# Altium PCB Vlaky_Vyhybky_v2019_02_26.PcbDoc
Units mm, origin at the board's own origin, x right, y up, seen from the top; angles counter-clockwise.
Board outline 140 x 100 mm, 2 copper layers (Top Layer, Bottom Layer); 83 components, 61 nets, 264 pads, 44 vias.
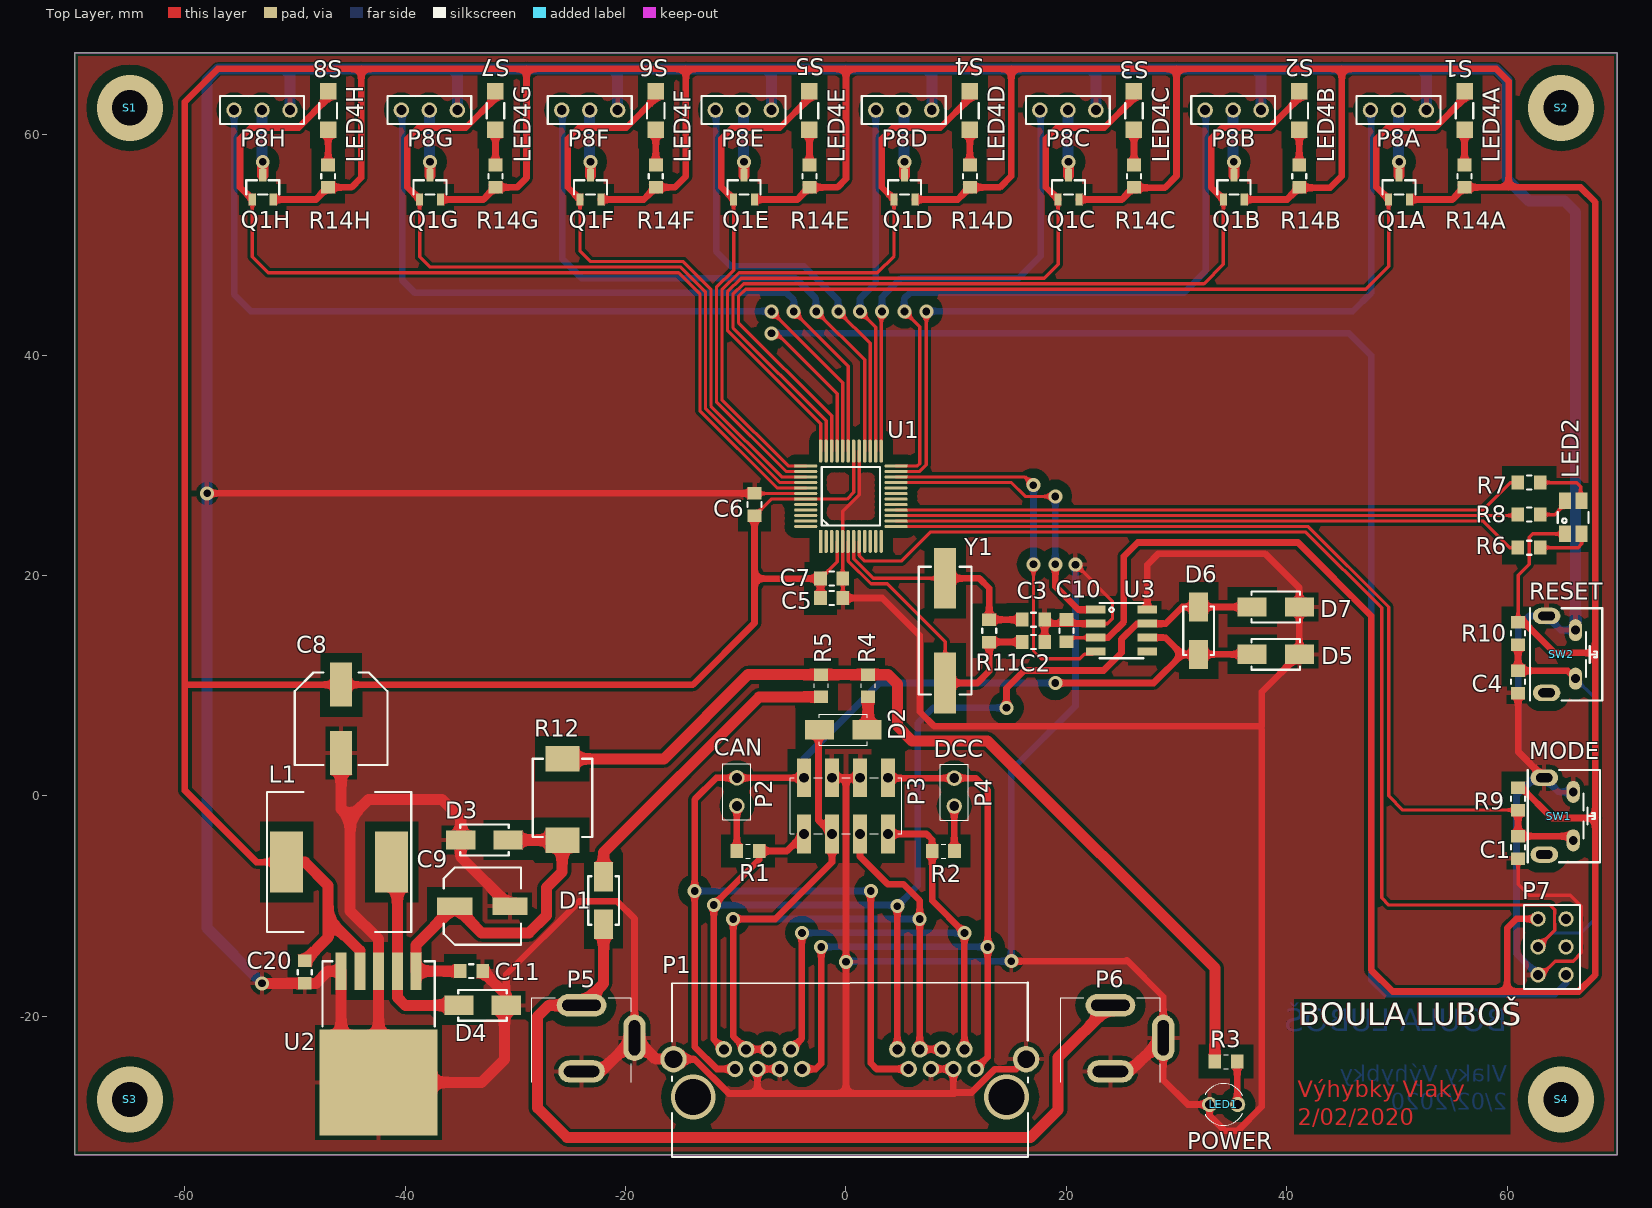
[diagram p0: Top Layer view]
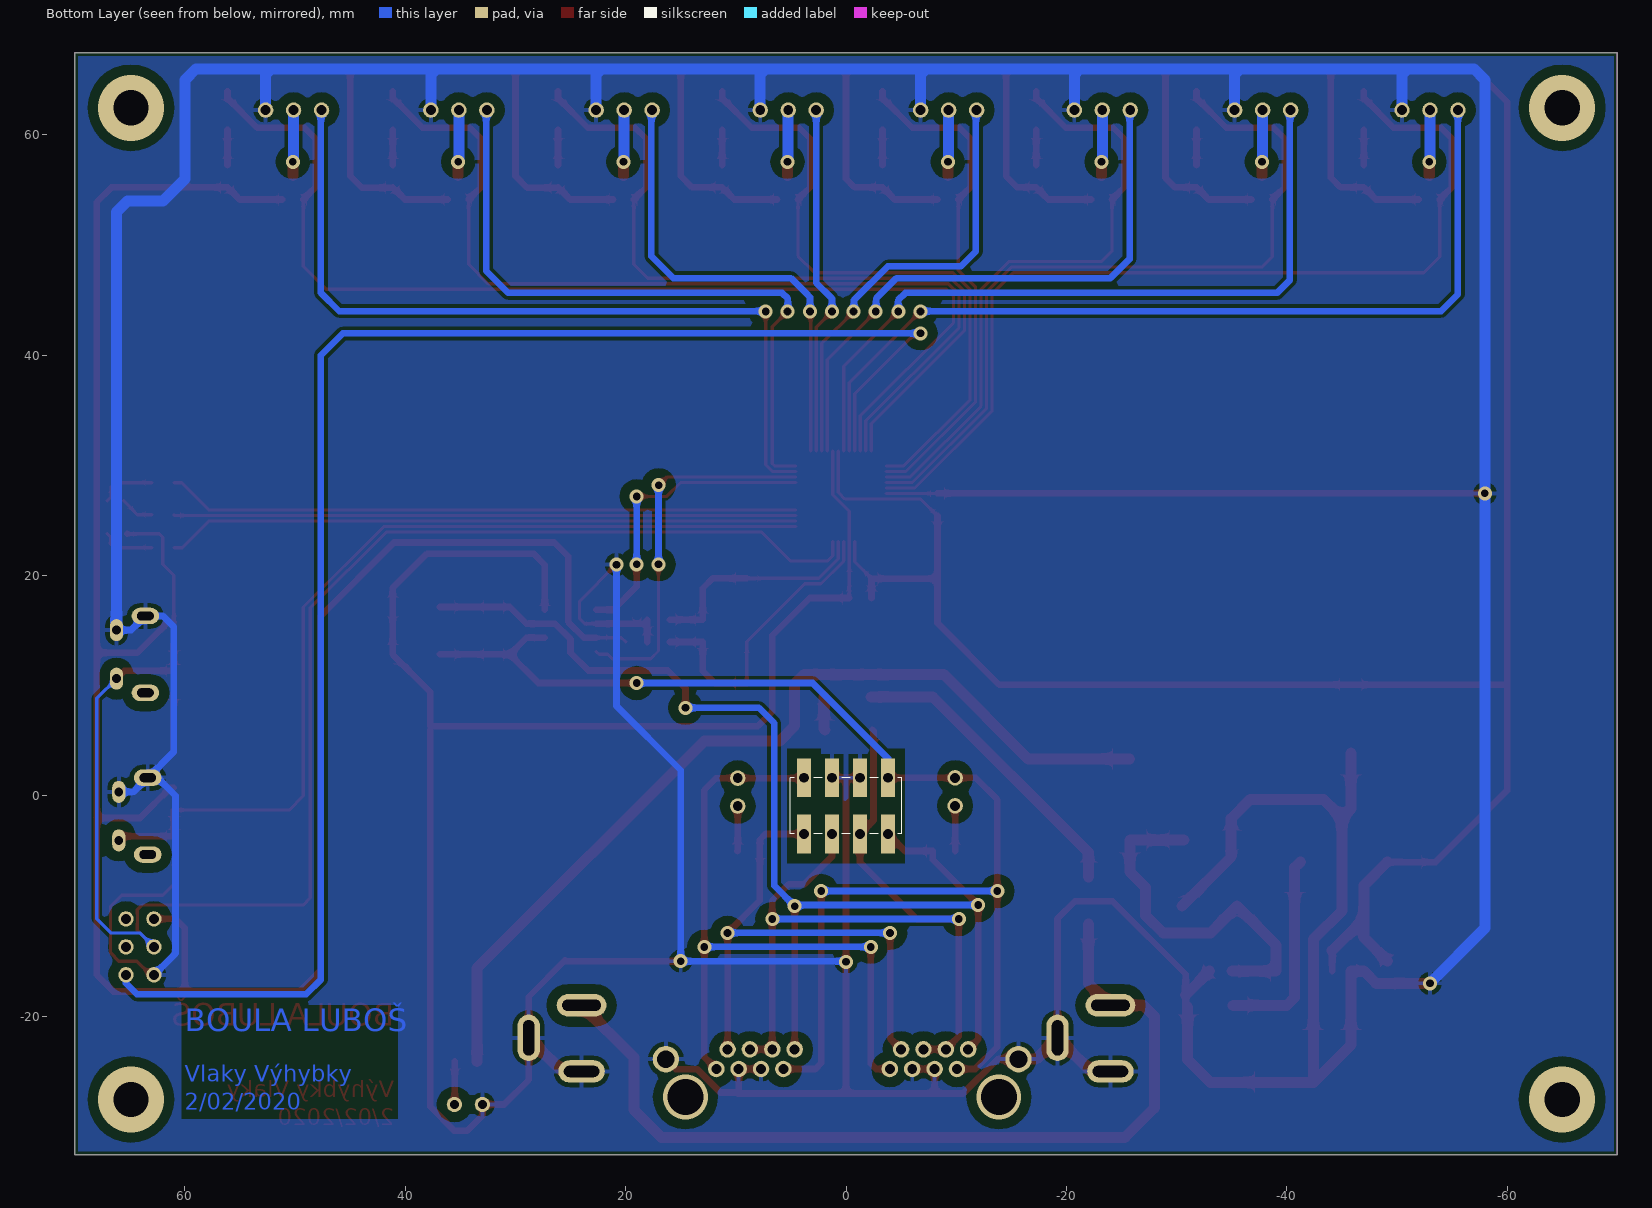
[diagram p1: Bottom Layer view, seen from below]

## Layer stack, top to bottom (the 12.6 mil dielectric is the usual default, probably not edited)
Top Solder: solder mask 0.0102, Solder Resist, Dk 3.5
Top Layer: signal copper 0.0356
Dielectric 1: dielectric 0.32, FR-4, Dk 4.8
Bottom Layer: signal copper 0.0356
Bottom Solder: solder mask 0.0102, Solder Resist, Dk 3.5

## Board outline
-70,-32.545 -70,67.455 70,67.455 70,-32.545

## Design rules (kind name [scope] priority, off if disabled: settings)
Clearance "Stitching No Net" [IsStitchingVia and InNet('No Net') vs (IsVia and (Not IsStitchingVia)) Or IsPad] p1: gap=0.127 ignorepadtopadclearanceinfootprint=FALSE
Clearance [All] p2: gap=0.2 ignorepadtopadclearanceinfootprint=FALSE except(0: Arc-Hole Track-Hole SMDPad-Hole THPad-Hole Via-Hole Fill-Hole Poly-Hole Region-Hole Text-Hole; 0.3: Arc-Poly Track-Poly Fill-Poly Poly-Poly Poly-Region Poly-Text; 0.9: SMDPad-Poly THPad-Poly Via-Poly)
Height [All] p1: minheight=0 maxheight=50 prefheight=10
HoleSize [All] p1: absolutevalues=TRUE maxlimit=3.6 minlimit=0.6 maxpercent=80.000 minpercent=20.000
MinimumSolderMaskSliver [All] p1: minsoldermaskwidth=0.1
PlaneConnect [All] p1: planeconnectstyle=Relief reliefexpansion=0.508 reliefentries=4 reliefconductorwidth=0.4 reliefairgap=0.3
PolygonConnect [All] p1: connectstyle=Relief reliefconductorwidth=0.4 reliefentries=4 polygonreliefangle="90 Angle" airgapwidth=0.4
RoomDefinition Connector [InComponentClass('Connector')] p1: confinementstyle=ConfineIn formatcopy=TRUE lockcomponents=FALSE outline -36,-33 38,-33 38,14 -36,14
RoomDefinition U_servo_2 [InComponentClass('U_servo_2')] p2: confinementstyle=ConfineIn formatcopy=TRUE lockcomponents=FALSE outline 31.137,75.25 31.137,49.25 42.137,49.25 42.137,75.25
RoomDefinition U_servo_4 [InComponentClass('U_servo_4')] p3: confinementstyle=ConfineIn formatcopy=TRUE lockcomponents=FALSE outline 1.244,75.25 1.244,49.25 12.244,49.25 12.244,75.25
RoomDefinition U_servo_8 [InComponentClass('U_servo_8')] p4: confinementstyle=ConfineIn formatcopy=TRUE lockcomponents=FALSE outline -57,75.25 -57,49.25 -46,49.25 -46,75.25
RoomDefinition U_servo_7 [InComponentClass('U_servo_7')] p5: confinementstyle=ConfineIn formatcopy=TRUE lockcomponents=FALSE outline -41.814,75.25 -41.814,49.25 -30.814,49.25 -30.814,75.25
RoomDefinition U_servo_6 [InComponentClass('U_servo_6')] p6: confinementstyle=ConfineIn formatcopy=TRUE lockcomponents=FALSE outline -27.26,75.25 -27.26,49.25 -16.26,49.25 -16.26,75.25
RoomDefinition U_servo_5 [InComponentClass('U_servo_5')] p7: confinementstyle=ConfineIn formatcopy=TRUE lockcomponents=FALSE outline -13.314,75.25 -13.314,49.25 -2.314,49.25 -2.314,75.25
RoomDefinition U_servo_3 [InComponentClass('U_servo_3')] p8: confinementstyle=ConfineIn formatcopy=TRUE lockcomponents=FALSE outline 16.137,75.25 16.137,49.25 27.137,49.25 27.137,75.25
RoomDefinition U_servo_1 [InComponentClass('U_servo_1')] p9: confinementstyle=ConfineIn formatcopy=TRUE lockcomponents=FALSE outline 46.137,75.25 46.137,49.25 57.137,49.25 57.137,75.25
RoutingVias [All] p1: holewidth=0.7 width=1.27 viastyle="Through Hole" minholewidth=0.7 minwidth=1.27 maxholewidth=0.7 maxwidth=1.27
ShortCircuit ShortCircuit_Text [InPolygon vs IsText] p1: allowed=TRUE
ShortCircuit [All] p2: allowed=FALSE
SilkToSilkClearance [All] p1: silktosilkclearance=0.1
SilkToSolderMaskClearance [IsPad] p1: minsilkscreentomaskgap=0.1 clearancetoexposedcopper=TRUE
SolderMaskExpansion [All] p1: expansion=0.1
Width [All] p1: maxlimit=1 minlimit=0.3 preferedwidth=0.6
23 further rules are at their usual default settings.

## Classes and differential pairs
channel class servo: U_servo_1 U_servo_2 U_servo_3 U_servo_4 U_servo_5 U_servo_6 U_servo_7 U_servo_8
component class U_servo_8: LED4H P8H Q1H R14H
component class U_servo_7: LED4G P8G Q1G R14G
component class U_servo_6: LED4F P8F Q1F R14F
component class U_servo_5: LED4E P8E Q1E R14E
component class U_servo_4: LED4D P8D Q1D R14D
component class U_servo_3: LED4C P8C Q1C R14C
component class U_servo_2: LED4B P8B Q1B R14B
component class U_servo_1: LED4A P8A Q1A R14A
component class main: S1 S2 S3 S4
component class Connector: D1 D2 LED1 P1 P2 P3 P4 P5 P6 R1 R2 R3 R4 R5
component class U_MCU: C1 C2 C3 C4 C5 C6 C7 LED2 P7 R6 R7 R8 R9 R10 R11 SW1 SW2 U1 Y1
component class U_CAN: C10 D5 D6 D7 U3
component class Power: C8 C9 C11 C20 D3 D4 L1 R12 U2

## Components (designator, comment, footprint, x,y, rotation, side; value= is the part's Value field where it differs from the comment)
C1 "100nF" SMD_CAPACITOR_0805 61,-4.665 r90 top
C2 "22pF" SMD_CAPACITOR_0805 17.015,13.97 r0 top
C3 "22pF" SMD_CAPACITOR_0805 17.015,16 r0 top
C4 "100nF" SMD_CAPACITOR_0805 61,10.35 r90 top
C5 "100nF" SMD_CAPACITOR_0805 -1.302,17.965 r180 top
C6 "100nF" SMD_CAPACITOR_0805 -8.3,26.45 r270 top
C7 "100nF" SMD_CAPACITOR_0805 -1.302,19.73 r180 top
C8 "470uF/10V" SMD_CAPACITOR_E_8MM -45.824,7 r0 top
C9 "100uF/35V" SMD_CAPACITOR_D_6.3MM -33,-10 r90 top
C10 "1uF" SMD_CAPACITOR_0805 20,15 r90 top
C11 "100nF/50V" SMD_CAPACITOR_0805 -34,-15.9 r180 top
C20 "100nF/50V" SMD_CAPACITOR_0805 -49.124,-15.985 r90 top
D1 "B340A-E3/61T" SMD_DO-214AC -22,-9.486 r90 top
D2 "B340A-E3/61T" SMD_DO-214AC -0.25,6 r0 top
D3 "SMA6J5.0CA" SMD_DO-214AC -32.814,-4 r0 top
D4 "B340A-E3/61T" SMD_DO-214AC -32.985,-19 r180 top
D5 "SMA6J12.0CA" SMD_DO-214AC 39,12.85 r0 top
D6 "SMA6J12.0CA" SMD_DO-214AC 32,15 r270 top
D7 "SMA6J12.0CA" SMD_DO-214AC 39,17.15 r180 top
L1 "100uH/3A" SMD_INDUCTOR_12.5MM -46,-6 r270 top
LED1 "Green" THT_LED_3MM 34.27,-28 r180 top
LED2 "ASMB-MTB0-0A3A2" SMD_LED_RGB 66,25.285 r0 top
LED4A "RED" SMD_LED_1206 56.137,62.205 r90 top (schematic designator LED4)
LED4B "RED" SMD_LED_1206 41.137,62.205 r90 top (schematic designator LED4)
LED4C "RED" SMD_LED_1206 26.137,62.205 r90 top (schematic designator LED4)
LED4D "RED" SMD_LED_1206 11.244,62.205 r90 top (schematic designator LED4)
LED4E "RED" SMD_LED_1206 -3.314,62.205 r90 top (schematic designator LED4)
LED4F "RED" SMD_LED_1206 -17.26,62.205 r90 top (schematic designator LED4)
LED4G "RED" SMD_LED_1206 -31.814,62.205 r90 top (schematic designator LED4)
LED4H "RED" SMD_LED_1206 -47,62.205 r90 top (schematic designator LED4)
P1 "RJ45 2PORT" THT_RJ45_2PORT -15.785,-32.78 r0 top
P2 "Header 1x2" THT_HEADER_100MIL_1X2_MALE -9.905,0.37 r180 top
P3 "Header 2x4" SMD_HEADER_100MIL_2X4_DOUBLESIDED 0,-0.9 r90 top
P4 "Header 1x2" THT_HEADER_100MIL_1X2_MALE 9.825,0.35 r180 top
P5 "Power JACK 2.1/2.5" THT_POWER_JACK_2.1/2.5 -21.6,-22 r270 top locked
P6 "Power JACK 2.1/2.5" THT_POWER_JACK_2.1/2.5 26.4,-22 r270 top locked
P7 "Header 2x3" THT_HEADER_100MIL_2X3_MALE 64.08,-13.7 r0 top
P8A "Header 1x3" THT_HEADER_100MIL_1X3_MALE_90 50.137,62.25 r90 top (schematic designator P8)
P8B "Header 1x3" THT_HEADER_100MIL_1X3_MALE_90 35.137,62.25 r90 top (schematic designator P8)
P8C "Header 1x3" THT_HEADER_100MIL_1X3_MALE_90 20.137,62.25 r90 top (schematic designator P8)
P8D "Header 1x3" THT_HEADER_100MIL_1X3_MALE_90 5.244,62.25 r90 top (schematic designator P8)
P8E "Header 1x3" THT_HEADER_100MIL_1X3_MALE_90 -9.314,62.25 r90 top (schematic designator P8)
P8F "Header 1x3" THT_HEADER_100MIL_1X3_MALE_90 -23.26,62.25 r90 top (schematic designator P8)
P8G "Header 1x3" THT_HEADER_100MIL_1X3_MALE_90 -37.814,62.25 r90 top (schematic designator P8)
P8H "Header 1x3" THT_HEADER_100MIL_1X3_MALE_90 -53,62.25 r90 top (schematic designator P8)
Q1A "IRLML6402TRPBF" SMD_SOT-23 50.201,55.235 r0 top (schematic designator Q1)
Q1B "IRLML6402TRPBF" SMD_SOT-23 35.201,55.235 r0 top (schematic designator Q1)
Q1C "IRLML6402TRPBF" SMD_SOT-23 20.201,55.235 r0 top (schematic designator Q1)
Q1D "IRLML6402TRPBF" SMD_SOT-23 5.308,55.235 r0 top (schematic designator Q1)
Q1E "IRLML6402TRPBF" SMD_SOT-23 -9.25,55.235 r0 top (schematic designator Q1)
Q1F "IRLML6402TRPBF" SMD_SOT-23 -23.196,55.235 r0 top (schematic designator Q1)
Q1G "IRLML6402TRPBF" SMD_SOT-23 -37.75,55.235 r0 top (schematic designator Q1)
Q1H "IRLML6402TRPBF" SMD_SOT-23 -52.936,55.235 r0 top (schematic designator Q1)
R1 "120" SMD_RESISTOR_0805 -8.89,-5 r0 top
R2 "120" SMD_RESISTOR_0805 8.835,-5 r180 top
R3 "2k2" SMD_RESISTOR_0805 34.493,-24.105 r180 top
R4 "0" SMD_RESISTOR_0805 2,10 r270 top
R5 "0" SMD_RESISTOR_0805 -2.25,10 r270 top
R6 "270" SMD_RESISTOR_0805 62,22.535 r0 top
R7 "270" SMD_RESISTOR_0805 62,28.44 r0 top
R8 "270" SMD_RESISTOR_0805 62,25.535 r0 top
R9 "10K" SMD_RESISTOR_0805 61,-0.265 r90 top value=10k
R10 "10K" SMD_RESISTOR_0805 61,14.75 r90 top value=10k
R11 "1M" SMD_RESISTOR_0805 13,14.985 r270 top
R12 "MF-SM300-2" SMD_RESISTOR_PTC_MF-SM -25.736,-0.329 r270 top
R14A "1K" SMD_RESISTOR_0805 56.137,56.25 r270 top value=1k (schematic designator R14)
R14B "1K" SMD_RESISTOR_0805 41.137,56.25 r270 top value=1k (schematic designator R14)
R14C "1K" SMD_RESISTOR_0805 26.137,56.25 r270 top value=1k (schematic designator R14)
R14D "1K" SMD_RESISTOR_0805 11.244,56.25 r270 top value=1k (schematic designator R14)
R14E "1K" SMD_RESISTOR_0805 -3.314,56.25 r270 top value=1k (schematic designator R14)
R14F "1K" SMD_RESISTOR_0805 -17.26,56.25 r270 top value=1k (schematic designator R14)
R14G "1K" SMD_RESISTOR_0805 -31.814,56.25 r270 top value=1k (schematic designator R14)
R14H "1K" SMD_RESISTOR_0805 -47,56.25 r270 top value=1k (schematic designator R14)
S1 "Hex Spacer M3" THT_HEX_SPACER_M3L20 -65,62.455 r0 top locked
S2 "Hex Spacer M3" THT_HEX_SPACER_M3L20 64.897,62.455 r0 top locked
S3 "Hex Spacer M3" THT_HEX_SPACER_M3L20 -65,-27.545 r0 top locked
S4 "Hex Spacer M3" THT_HEX_SPACER_M3L20 64.897,-27.545 r0 top locked
SW1 "Switch 90" THT_SWITCH_SPST_90 64.687,-1.829 r270 top
SW2 "Switch 90" THT_SWITCH_SPST_90 64.897,12.85 r270 top
U1 "MC9S08DZ60" SMD_LQFP-48 0.448,27.2 r90 top
U2 "LM2576-5.0" SMD_TO-263-5 -42.424,-15.9 r180 top
U3 "MCP2551" SMD_SOIC-8 25,15 r0 top
Y1 "8Mhz" SMD_XTAL_HC-49 9,15 r270 top

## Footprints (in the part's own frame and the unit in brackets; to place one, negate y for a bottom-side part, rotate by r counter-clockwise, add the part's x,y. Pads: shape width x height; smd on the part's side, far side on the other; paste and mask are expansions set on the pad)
SMD_CAPACITOR_0805 [mm]
  rect 1.14x1.27 smd: 1(-1.015,0) 2(1.015,0)
  silkscreen extent -0.2,-0.64 0.2,0.63, body extent -1,-0.6 1,0.6, height 1.18
SMD_CAPACITOR_D_6.3MM [mm]
  rect 1.6x3.2 smd: 1(0,2.5) 2(0,-2.5)
  silkscreen extent -3.5,-3.5 3.5,3.5, body extent -3.3,-3.5 3.3,3.5, height 7.71
SMD_CAPACITOR_E_8MM [mm]
  rect 2x4 smd: 1(0,3.1) 2(0,-3.1)
  silkscreen extent -4.2,-4.2 4.2,4.2, body extent -4.15,-4.95 4.15,4.95, height 10.21
SMD_DO-214AC [mm]
  rect 2.65x1.75 smd: 1(-2.15,0) 2(2.15,0)
  silkscreen extent -2.2,-1.4 2.2,1.4, body extent -2.5,-1.35 2.5,1.35, height 2.19
SMD_HEADER_100MIL_2X4_DOUBLESIDED [mm]
  rect 3.5x1.27 hole 0.9 mask+0.05: 1(-2.55,3.81) 2(2.55,3.81) 3(-2.55,1.27) 4(2.55,1.27) 5(-2.55,-1.27) 6(2.55,-1.27) 7(-2.55,-3.81) 8(2.55,-3.81)
  silkscreen extent -2.54,-5.08 2.54,5.08, body extent -3.75,-5.08 3.75,5.08, height 9.57
SMD_INDUCTOR_12.5MM [mil]
  rect 217x118 smd: 1(0,187.5) 2(0,-187.5)
  silkscreen extent -250,-258 250,257, body extent -242,-242 242,242, height 402
SMD_LED_1206 [mm]
  rect 1.5x1.5 smd mask+0.1: 1(-1.75,0) 2(1.75,0)
  silkscreen extent -0.7,-0.8 0.7,0.8, body extent -1.6,-0.8 1.6,0.8, height 1.1
SMD_LED_RGB [mm]
  rect 1.1x1.5 smd: 1(-0.75,-1.5) 2(-0.75,1.5) 3(0.75,1.5) 4(0.75,-1.5)
  silkscreen extent -1.4,-0.5 1.4,0.5, body extent -1.4,-1.6 1.4,1.6, height 1.91
SMD_LQFP-48 [mm]
  rect 2.1x0.3 smd: 1(-4.1,2.75)
  oval 2.1x0.3 smd: 2(-4.1,2.25) 3(-4.1,1.75) 4(-4.1,1.25) 5(-4.1,0.75) 6(-4.1,0.25) 7(-4.1,-0.25) 8(-4.1,-0.75) 9(-4.1,-1.25) 10(-4.1,-1.75) 11(-4.1,-2.25) 12(-4.1,-2.75) 25(4.1,-2.75) 26(4.1,-2.25) 27(4.1,-1.75) 28(4.1,-1.25) 29(4.1,-0.75) 30(4.1,-0.25) 31(4.1,0.25) 32(4.1,0.75) 33(4.1,1.25) 34(4.1,1.75) 35(4.1,2.25) 36(4.1,2.75)
  oval 0.3x2.1 smd: 13(-2.75,-4.1) 14(-2.25,-4.1) 15(-1.75,-4.1) 16(-1.25,-4.1) 17(-0.75,-4.1) 18(-0.25,-4.1) 19(0.25,-4.1) 20(0.75,-4.1) 21(1.25,-4.1) 22(1.75,-4.1) 23(2.25,-4.1) 24(2.75,-4.1) 37(2.75,4.1) 38(2.25,4.1) 39(1.75,4.1) 40(1.25,4.1) 41(0.75,4.1) 42(0.25,4.1) 43(-0.25,4.1) 44(-0.75,4.1) 45(-1.25,4.1) 46(-1.75,4.1) 47(-2.25,4.1) 48(-2.75,4.1)
  silkscreen extent -2.65,-2.65 2.65,2.65, body extent -4.51,-4.51 4.51,4.51, height 1.1
SMD_RESISTOR_0805 [mm]
  rect 1.14x1.27 smd: 1(-1.015,0) 2(1.015,0)
  silkscreen extent -0.2,-0.64 0.2,0.63, body extent -1,-0.64 1,0.64, height 0.61
SMD_RESISTOR_PTC_MF-SM [mm]
  rect 2.3x3.1 smd: 1(-3.7,0) 2(3.7,0)
  silkscreen extent -3.7,-2.7 3.4,2.7, body extent -3.68,-2.72 3.68,2.72, height 3.18
SMD_SOIC-8 [mm]
  rect 1.78x0.72 smd: 1(-2.34,1.905) 2(-2.34,0.635) 3(-2.34,-0.635) 4(-2.34,-1.905) 5(2.34,-1.905) 6(2.34,-0.635) 7(2.34,0.635) 8(2.34,1.905)
  silkscreen extent -2,-2.5 2,2.5, body extent -3,-2.45 3,2.45, height 1.75
SMD_SOT-23 [mm]
  rect 0.65x1.1 smd: 1(-0.95,-1.1) 2(0.95,-1.1) 3(0,1.1)
  silkscreen extent -1.5,-0.65 1.5,0.65, body extent -1.5,-1.13 1.5,1.13, height 1.22
SMD_TO-263-5 [mm]
  rect 1x3.4 smd mask+0.05: 1(-3.4,0) 2(-1.7,0) 3(0,0) 4(1.7,0) 5(3.4,0)
  rect 10.7x9.6 smd mask+0.05: 3(0,10.1)
  silkscreen extent -5.1,-0.9 5.1,5, body extent -5.08,-0.87 5.08,13.77, height 4.57
SMD_XTAL_HC-49 [mm]
  rect 5.5x2 smd: 1(-4.75,0)
  rect 5.5x2 smd mask+0.1: 2(4.75,0)
  silkscreen extent -5.8,-2.4 5.8,2.4, body extent -6.4,-2.41 6.4,2.42, height 4.3
THT_HEADER_100MIL_1X2_MALE [mm]
  round 1.4 hole 0.9: 1(0,1.27) 2(0,-1.27)
  silkscreen extent -1.27,-2.54 1.27,2.54, body extent -1.27,-2.54 1.27,2.54, height 8.54
THT_HEADER_100MIL_1X3_MALE_90 [mm]
  round 1.4 hole 0.9: 1(0,2.54) 2(0,0) 3(0,-2.54)
  silkscreen extent -1.27,-3.81 1.27,3.81, body extent -0.3,-3.61 9.78,3.61, height 2.45
THT_HEADER_100MIL_2X3_MALE [mm]
  round 1.4 hole 0.9: 1(-1.27,2.54) 2(1.27,2.54) 3(-1.27,0) 4(1.27,0) 5(-1.27,-2.54) 6(1.27,-2.54)
  silkscreen extent -2.54,-3.81 2.54,3.81, body extent -2.54,-3.81 2.54,3.81, height 8.54
THT_HEX_SPACER_M3L20 [mm]
  body extent -2.5,-2.89 2.5,2.89, height 5.58
THT_LED_3MM [mm]
  round 1.4 hole 0.8: 1(-1.27,0) 2(1.27,0)
  silkscreen extent -1.72,-1.9 1.61,1.9, body extent -1.9,-1.9 1.6,1.9, height 5.6
THT_POWER_JACK_2.1/2.5 [mil]
  oval 80x178 hole 40 slot 138 at 90 deg: 1(-118.11,-94.49)
  oval 166x80 hole 40 slot 126 at 0 deg: 2(-1.97,94.49)
  oval 80x166 hole 40 slot 126 at 90 deg: 3(118.11,-94.49)
  silkscreen extent -146,-272 157,83, body extent -144,-272 407,98, height 433
THT_RJ45_2PORT [mm]
  round 2.4 hole 1.6: 0(0.13,8.89) 0(32.13,8.89)
  round 1.5 hole 0.9: 1(4.695,9.78) 2(5.715,8) 3(6.725,9.78) 4(7.745,8) 5(8.755,9.78) 6(9.775,8) 7(10.785,9.78) 8(11.805,8) 9(20.445,9.78) 10(21.465,8) 11(22.475,9.78) 12(23.495,8) 13(24.505,9.78) 14(25.525,8) 15(26.535,9.78) 16(27.555,8)
  silkscreen extent 0,0 32.3,15.85, body extent 0,0 32.3,15.85, height 13.46
THT_SWITCH_SPST_90 [mm]
  oval 2x1.2 hole 0.8: 1(-2.2,1.313) 2(2.2,1.313)
  oval 1.5x2.5 hole 0.8 slot 1.5 at 90 deg: 3(-3.486,-1.312) 4(3.486,-1.312)
  silkscreen extent -4.18,-2.81 4.18,3.74, body extent -4.18,-2.81 4.18,5.16, height 7.37

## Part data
C1 C2 C3 C4 C5 C6 C7 C10 C11 C20: library part Capacitor, "Capacitor"
C8 C9: library part Capacitor_POL, "Capacitor_POL"
D1 D2 D4: library part Diode_Schottky, "Diode Schottky"
D3 D5 D6 D7: library part Transil, "Transient Voltage Suppressor, Bidirectional"
L1: library part Inductor, "Inductor"
LED1 LED4A LED4B LED4C LED4D LED4E LED4F LED4G LED4H: library part LED, "LED"
LED2: library part LED_RGB, "LED RGB"
P1: library part RJ45_2PORT, "RJ45 - 2 port"
P2 P4: library part Header_1x2
P3: library part Header_2x4_Trains_Project
P5 P6: library part Power_JACK_2.1/2.5, "Low Voltage Power Supply Connector"
P7: library part Header_2x3
P8A P8B P8C P8D P8E P8F P8G P8H: library part Header_1x3
Q1A Q1B Q1C Q1D Q1E Q1F Q1G Q1H: library part Transistor_MOSFET_P, "Transistor MOSFET P"
R1 R2 R3 R4 R5 R6 R7 R8 R9 R10 R11 R14A R14B R14C R14D R14E R14F R14G R14H: library part Resistor, "Resistor"
R12: library part Resistor_PTC, "Resistor PTC"
S1 S2 S3 S4: library part HEX_SPACER_M3, "Hexagon metal spacer M3"
SW1 SW2: library part Switch_90, "Tactile Switch Right Angle"
U1: library part MC9S08DZ96, "NXP 8 Bit Microcontroller, CAN"
U2: "Step Down Switching Regulator, Fixed, 4V-40V Input, 5V and 3A Output"
U3: "CAN Transceiver, 4.5 V - 5.5 V, 1 Mb/s"
Y1: library part XTAL, "Crystal Oscillator"

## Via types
v1: diameter 1.27, hole 0.7, Top Layer to Bottom Layer, tented both sides, 38 vias
v2: diameter 6, hole 3.2, Top Layer to Bottom Layer, 4 vias
v3: diameter 4.05, hole 3.25, Top Layer to Bottom Layer, 2 vias

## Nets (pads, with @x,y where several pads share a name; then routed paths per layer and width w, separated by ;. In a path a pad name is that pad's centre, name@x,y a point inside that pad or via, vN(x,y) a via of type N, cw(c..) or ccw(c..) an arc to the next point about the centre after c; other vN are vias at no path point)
+5V: C5.2 C6.2 C7.2 C8.1 C10.1 C20.2 L1.2 LED2.1 P7.1 Q1A.2 Q1B.2 Q1C.2 Q1D.2 Q1E.2 Q1F.2 Q1G.2 Q1H.2 R9.2 R10.2 R14A.2 R14B.2 R14C.2 R14D.2 R14E.2 R14F.2 R14G.2 R14H.2 U1.4 U1.30 U1.43 U2.4 U3.3 | length 662.8
  Top Layer w0.3: C6.2 -6.785,26.95 0.093,26.95 0.698,27.556 U1.30 ; C7.2 -0.802,21.245 U1.4 ; C10.1 20.38,14.365 U3.3 ; R10.2 61,20.022 62,21.022 62,23.473 62.313,23.785 LED2.1
  Top Layer w0.6: Q1H.2 -48.1,54.135 R14H.2 -44.889,55.235 -44,56.124 -44,66 ; -49.124,-6 L1.2 -53.514,-6 -60,0.486 -60,10 ; U2.4 -44.124,-14.046 ; Q1G.2 -32.914,54.135 R14G.2 -29.865,55.235 -29,56.1 -29,66 ; Q1F.2 -18.36,54.135 R14F.2 -15.545,55.235 -14.529,56.251 -14.529,66 ; C6.2 -8.3,19.73 ; Q1E.2 -4.414,54.135 R14E.2 -0.78,55.235 0,56.015 0,66 ; C5.2 C7.2 -8.3,19.73 ; Q1D.2 10.144,54.135 R14D.2 13.97,55.235 15,56.265 15,66 ; Q1C.2 25.037,54.135 R14C.2 ; U3.3 23.788,14.365 25.222,15.799 25.222,21.751 26.471,23 41.022,23 47.661,16.361 47.661,-15.79 49.621,-17.75 60,-17.75 ; R14C.2@26.137,55.205 28.94,55.205 30,56.265 30,66 ; Q1B.2 40.037,54.135 R14B.2 ; R14B.2@41.137,55.205 43.94,55.205 45,56.265 45,66 ; Q1A.2 55.037,54.135 R14A.2 60.135,55.235 ; R9.2 61.33,0.75 64.08,-2 68,-2 ; R10.2 61.547,15.765 64.313,13 68,13 ; P7.1@62.65,-11 P7.1 60.84,-11.16 60,-12 60,-17.75 ; -60,10 -60,11 -60,63 -57,66 -44,66 ; -60,10 -59.9,10.1 C8.1 -13.9,10.1 -8.3,15.7 -8.3,19.73 ; -44,66 -29,66 ; -29,66 -14.529,66 ; -14.529,66 0,66 ; 0,66 15,66 ; 15,66 30,66 ; 30,66 45,66 ; 45,66 59,66 60.135,64.865 60.135,55.235 ; 60,-17.75 66.49,-17.75 68,-16.24 68,-2 ; 60.135,55.235 66.665,55.235 68,53.9 68,13 ; 68,-2 68,13
  Top Layer w1: C20.2 -47,-12.846 -47,-11.17 ; -49.124,-6 -47,-8.124 -47,-11.17 ; -44.124,-14.046 -47,-11.17
+24V: R3.2 R4.1 R5.1 R12.1 | length 84.1
  Top Layer w1: R12.1 -16.529,3.371 -8.885,11.015 R5.1 R4.1 3.81,11.015 4.66,10.165 4.66,6.34 6,5 12.858,5 33.478,-15.62 R3.2
+24V_ETH: D2.1 P1.3 P1.5 P1.11 P1.13 P3.3 P3.5 | length 79.7
  Top Layer w0.6: P1.5 P1.3 -10.237,-21.823 v1(-10.237,-11.17) -6.42,-11.17 -1.27,-6.02 P3.3 -2.5,-2.22 -2.5,5.9 D2.1 ; P3.5 1.27,-5.49 3.78,-8 5.19,-8 6.69,-9.5 v1(6.69,-11.17) P1.11 P1.13
  Bottom Layer w0.6: v1(-10.237,-11.17) 6.52,-11.17 v1@6.69,-11
+24V_JACK: D1.1 P5.1 P6.1 | length 81.8
  Top Layer w1: D1.1 -22,-17 P5.1 -27,-19 -28,-20 -28,-28.3 -25.3,-31 16.76,-31 19.25,-28.51 19.25,-23.75 P6.1
BKGD: P7.6 U1.33 | length 144.7
  Top Layer w0.3: v1(-6.756,41.986) -6.288,41.986 -0.802,36.5 U1.33
  Bottom Layer w0.6: v1(-6.756,41.986) 45.675,41.986 47.661,40 47.661,-16.661 49,-18 64.35,-18 65.35,-17 P7.6
BUTTON: C1.2 R9.1 SW1.2 U1.13 | length 84.7
  Top Layer w0.3: U1.13 41.951,24.45 49.251,17.15 49.251,0 50.531,-1.28 R9.1
  Top Layer w0.6: R9.1 C1.2 65.621,-3.65 SW1.2
CAN_H: D6.1 D7.2 P1.1 P1.9 P3.1 R1.2 U3.7 | length 108.3
  Top Layer w0.6: P1.1 -12,-22.09 v1(-12,-9.9) -7.875,-5.775 R1.2 -5.36,-5 P3.1 ; P1.9 v1(4.66,-10) ; v1(14.57,8) 14.57,9.77 16.185,11.385 23.385,11.385 25,13 25,14.234 26.401,15.635 U3.7 29,15.635 30.515,17.15 D6.1 D7.2
  Bottom Layer w0.6: v1(-12,-9.9) 4.56,-9.9 v1(4.66,-10) 6.52,-8.14 6.52,6.61 7.91,8 v1(14.57,8)
CAN_L: D5.1 D6.2 P1.2 P1.10 P2.2 P3.2 U3.6 | length 123.2
  Top Layer w0.6: P1.2 -11.718,-24.78 -13.739,-22.759 v1(-13.739,-8.63) -13.739,-0.329 -11.77,1.64 P2.2 -3.82,1.64 P3.2 ; v1(2.25,-8.63) 2.25,-24.25 2.78,-24.78 P1.10 ; v1(19,10.25) 27.915,10.25 30.515,12.85 ; U3.6 29,14.365 30.515,12.85 ; D5.1 D6.2 30.515,12.85
  Bottom Layer w0.6: v1(-13.739,-8.63) v1(2.25,-8.63) v1@2.398,-8.63 ; P3.2 -3.81,3.413 3.027,10.25 v1(19,10.25)
CAN_RX: U1.22 U3.4 | length 33.7
  Top Layer w0.3: U1.22 16.251,28.95 v1(17,28.201) ; v1@17.018,20.975 17.018,13.157 17.729,12.446 21.234,12.446 21.638,12.85 22.415,12.85 U3.4
  Bottom Layer w0.6: v1(17.018,21.022) v1@17.018,27.982
CAN_TX: U1.21 U3.1 | length 27.5
  Top Layer w0.3: U1.21 15,28.45 16.267,27.183 v1(19,27.183)
  Top Layer w0.6: v1@19,21 19,19 21.095,16.905 U3.1
  Bottom Layer w0.6: v1(19,21.022) v1@19,27
DCC+: P1.7 P1.15 P3.7 R2.2 | length 50.2
  Top Layer w0.6: P1.7 -4,-22 v1(-4,-12.43) ; P3.7 7.298,-3.45 7.82,-3.972 R2.2 7.82,-9.5 v1(10.75,-12.43) P1.15
  Bottom Layer w0.6: v1(-4,-12.43) v1(10.75,-12.43)
DCC-: P1.8 P1.16 P3.8 P4.2 | length 62.9
  Top Layer w0.6: P1.8 -2.75,-24.78 -2.25,-24.28 v1(-2.25,-13.7) ; P3.8 3.84,1.62 P4.2 11.77,1.62 12.858,0.532 v1(12.858,-13.7) 12.858,-23.692 P1.16
  Bottom Layer w0.6: v1(-2.25,-13.7) v1(12.858,-13.7)
GND: C1.1 C2.2 C3.2 C4.1 C5.1 C6.1 C7.1 C8.2 C9.2 C10.2 C11.1 C20.1 D3.1 D4.1 D5.2 D7.1 LED1.2 P1.0 P1.4 P1.6 P1.12 P1.14 P3.4 P3.6 P5.2 P5.3 P6.2 P6.3 P7.5 P8A.3 P8B.3 P8C.3 P8D.3 P8E.3 P8F.3 P8G.3 P8H.3 SW1.1 SW1.3 SW2.1 SW2.3 U1.5 U1.29 U1.42 U2.3 U2.5 U3.2 U3.8 | length 899.6
  Top Layer w0.3: C6.1 -8.285,27.45 U1.42 ; C5.1 C7.1 -0.302,19.745 U1.5 -0.302,25.849 1.198,27.349 U1.29 ; v1@20.93,20.93 24.181,17.678 24.181,16.086 23.73,15.635 U3.2 ; C1.1 61,-8 62,-9 65.74,-9 66.75,-10.01 66.75,-14.25 66,-15 64.361,-15 63.121,-16.24 P7.5
  Top Layer w0.6: v1(-57.985,27.465) C6.1 ; D4.1@-31,-19.165 D4.1 -30.835,-18.05 -30.835,-16.185 -24.2,-9.55 -20.777,-9.55 -19.2,-11.128 P5.2 ; P1.0@-15.655,-23.89 -13.739,-23.89 -10.629,-27 -8.04,-27 ; P1.6 P1.4 -8.04,-27 ; P3.4 0,1.65 ; C5.1 3.298,17.965 6.69,14.573 6.69,7.65 8,6.34 37.741,6.34 37.741,9.441 D5.2 D7.1 41.15,18.872 38.022,22 28.365,22 27.34,20.975 U3.8 ; P3.6 0,1.65 ; P1.12 P1.14 9.74,-26.915 ; v1(15,-15) 25.38,-15 25.48,-14.9 28.8,-18.22 P6.2 28.8,-25.768 31.032,-28 LED1.2 33,-29 34.395,-30.395 35.54,-30.395 37.741,-28.194 37.741,6 ; P1.0@16.345,-23.89 15.44,-24.795 13.523,-24.795 11.403,-26.915 9.74,-26.915 ; C2.2 C3.2 18.395,15.635 U3.2 ; C4.1 61,4.032 SW1.3 ; -8.04,-27 0,-27 ; 0,-27 0,-12.559 0,1.65 ; 0,-27 9.825,-27 9.74,-26.915
  Top Layer w1: v1@-52.936,-17 C20.1 -48.1,-17 -47,-15.9 U2.5 -45.824,-22.6 U2.3@-42.424,-26 ; C8.2 -45.824,-1.176 -45,-2 ; C11.1 -30.835,-18.05 ; D4.1@-31,-19.165 -31,-23.93 -33.07,-26 U2.3@-42.424,-26 ; C9.2 -34.964,-5.536 D3.1 -34.964,-2.05 -36.685,-0.329 -43.329,-0.329 -45,-2 ; P5.3 -22.25,-25 P5.2 -17.26,-23.89 P1.0@-15.655,-23.89 ; P6.3 25.75,-25 P6.2 ; -45,-2 -45,-10.424 -42.424,-13 -42.424,-15.9 U2.3@-42.424,-26
  Bottom Layer w0.6: v1@0,-15 0.1,-14.9 0.2,-15 v1(15,-15) 15,2.339 20.828,8.167 v1(20.828,20.994) ; P7.5 60.858,-14.288 60.858,0.025 62.49,1.657 SW1.3 ; SW1.1 64.661,0.371 SW1.3 ; SW2.1 64.871,15.05 SW2.3 62,16.336 61,15.336 61,4.032 SW1.3
  Bottom Layer w1: v1(-53,-17) -58,-12 -58,65 -57,66 -51,66 ; P8H.3 -50.46,65.46 -51,66 ; -41.814,66 -35.814,66 -35.274,65.46 P8G.3 ; -27.26,66 -21.26,66 -20.72,65.46 P8F.3 ; -13.314,66 -7.314,66 -6.774,65.46 P8E.3 ; 1.244,66 7.244,66 7.784,65.46 P8D.3 ; 16.137,66 22.137,66 22.677,65.46 P8C.3 ; 31.137,66 37.137,66 37.677,65.46 P8B.3 ; 46.137,66 52.137,66 52.677,65.46 P8A.3 ; SW2.1 66.21,53 65.21,54 62,54 60,56 60,65 59,66 52.741,66 38,66 22.235,66 7.71,66 -7,66 -21,66 -35,66 -51,66
  other v1: 0,-15.048
LED_B: R8.1 U1.15 | length 56.5
  Top Layer w0.3: U1.15 60.985,25.45 R8.1
LED_G: R7.1 U1.16 | length 57.5
  Top Layer w0.3: U1.16 57.781,25.95 60.271,28.44 R7.1
LED_R: R6.1 U1.14 | length 57.4
  Top Layer w0.3: U1.14 57.835,24.95 60.25,22.535 R6.1
NetC2_1: C2.1 R11.2 U1.6 Y1.2 | length 27.5
  Top Layer w0.3: U1.6 0.198,21.993 0.198,21.322 2.27,19.25 3.75,19.25 9,14 Y1.2
  Top Layer w0.6: Y1.2 11.923,10.25 13,11.327 R11.2 C2.1
NetC3_1: C3.1 R11.1 U1.7 Y1.1 | length 20.8
  Top Layer w0.3: U1.7 0.698,21.529 2.477,19.75 Y1.1
  Top Layer w0.6: Y1.1 12.108,19.75 13,18.858 R11.1 C3.1
NetC9_1: C9.1 C11.2 D3.2 R12.2 U2.1 | length 33.7
  Top Layer w1: C11.2 U2.1 -39.024,-13.524 C9.1 -33.07,-12.43 -28.794,-12.43 -27.195,-10.831 -27.195,-8.319 -25.765,-6.889 -25.765,-4 D3.2
NetD1_2: D1.2 R5.2 | length 27.8
  Top Layer w1: D1.2 -22,-5.14 -7.875,8.985 R5.2
NetD2_2: D2.2 R4.2 | length 3
  Top Layer w1: D2.2 2,6.1 R4.2
NetD4_2: D4.2 L1.1 U2.2 | length 18.4
  Top Layer w1: L1.1 -40.724,-6.514 U2.2 -40.724,-18.276 -40,-19 -37.95,-19 D4.2
NetLED1_1: LED1.1 R3.1 | length 3.9
  Top Layer w0.6: R3.1 35.508,-27.968 LED1.1
NetLED2_2: LED2.2 R8.2 | length 3.1
  Top Layer w0.3: R8.2 64.313,25.535 LED2.2@65.563,26.785
NetLED2_3: LED2.3 R7.2 | length 5.3
  Top Layer w0.3: R7.2 66.312,28.44 66.675,28.078 66.675,27.173 LED2.3@67.063,26.785
NetLED2_4: LED2.4 R6.2 | length 4.9
  Top Layer w0.3: R6.2 66.455,22.535 66.75,22.83 66.75,23.473 LED2.4@67.063,23.785
NetLED4A_1: LED4A.1 R14A.1 | length 3.2
  Top Layer w0.6: R14A.1 LED4A.1
NetLED4A_2: LED4A.2 Q1A.1 U1.34 | length 99.6
  Top Layer w0.3: U1.34 -1.302,34.51 -9.759,42.967 -9.759,45.331 -9.09,46 47.161,46 49.251,48.09 Q1A.1@49.251,53.9
  Top Layer w0.6: Q1A.1 48.137,55.249 48.137,59.646 49.137,60.646 53.445,60.646 56.137,63.338 LED4A.2
NetLED4B_1: LED4B.1 R14B.1 | length 3.2
  Top Layer w0.6: R14B.1 LED4B.1
NetLED4B_2: LED4B.2 Q1B.1 U1.35 | length 85.1
  Top Layer w0.3: U1.35 -1.802,34.052 -10.259,42.509 -10.259,45.538 -9.297,46.5 32.5,46.5 34.251,48.251 Q1B.1@34.251,53.9
  Top Layer w0.6: Q1B.1 33.137,55.249 33.137,59.646 34.137,60.646 38.445,60.646 41.137,63.338 LED4B.2
NetLED4C_1: LED4C.1 R14C.1 | length 3.2
  Top Layer w0.6: R14C.1 LED4C.1
NetLED4C_2: LED4C.2 Q1C.1 U1.36 | length 71
  Top Layer w0.3: U1.36 -2.302,33.798 -10.759,42.255 -10.759,45.745 -9.504,47 18,47 19.251,48.251 Q1C.1@19.251,54.105
  Top Layer w0.6: Q1C.1 18.137,55.249 18.137,59.646 19.137,60.646 23.445,60.646 26.137,63.338 LED4C.2
NetLED4D_1: LED4D.1 R14D.1 | length 3.2
  Top Layer w0.6: R14D.1 LED4D.1
NetLED4D_2: LED4D.2 Q1D.1 U1.37 | length 58.2
  Top Layer w0.3: U1.37 -5.238,29.95 -11.259,35.971 -11.259,45.952 -9.711,47.5 2.858,47.5 4.358,49 Q1D.1@4.358,54.105
  Top Layer w0.6: Q1D.1 3.244,55.249 3.244,59.646 4.244,60.646 8.552,60.646 11.244,63.338 LED4D.2
NetLED4E_1: LED4E.1 R14E.1 | length 3.2
  Top Layer w0.6: R14E.1 LED4E.1
NetLED4E_2: LED4E.2 Q1E.1 U1.38 | length 45.8
  Top Layer w0.3: Q1E.1@-10.2,54.105 -10.2,47.718 -11.759,46.16 -11.759,35.764 -5.445,29.45 U1.38
  Top Layer w0.6: Q1E.1 -11.314,55.249 -11.314,59.646 -10.314,60.646 -6.006,60.646 -3.314,63.338 LED4E.2
NetLED4F_1: LED4F.1 R14F.1 | length 3.2
  Top Layer w0.6: R14F.1 LED4F.1
NetLED4F_2: LED4F.2 Q1F.1 U1.39 | length 56
  Top Layer w0.3: Q1F.1 -24.146,49.477 -23.169,48.5 -14.782,48.5 -12.259,45.977 -12.259,35.384 -5.825,28.95 U1.39
  Top Layer w0.6: Q1F.1 -25.26,55.249 -25.26,59.646 -24.26,60.646 -19.951,60.646 -17.26,63.338 LED4F.2
NetLED4G_1: LED4G.1 R14G.1 | length 3.2
  Top Layer w0.6: R14G.1 LED4G.1
NetLED4G_2: LED4G.2 Q1G.1 U1.40 | length 71
  Top Layer w0.3: Q1G.1@-38.7,54.105 -38.7,48.95 -37.75,48 -14.989,48 -12.759,45.77 -12.759,35.177 -6.032,28.45 U1.40
  Top Layer w0.6: Q1G.1 -39.814,55.249 -39.814,59.646 -38.814,60.646 -34.506,60.646 -31.814,63.338 LED4G.2
NetLED4H_1: LED4H.1 R14H.1 | length 3.2
  Top Layer w0.6: R14H.1 LED4H.1
NetLED4H_2: LED4H.2 Q1H.1 U1.41 | length 86.4
  Top Layer w0.3: Q1H.1 -53.886,48.95 -52.436,47.5 -15.196,47.5 -13.259,45.563 -13.259,34.97 -6.239,27.95 U1.41
  Top Layer w0.6: Q1H.1 -55,55.249 -55,59.646 -54,60.646 -49.692,60.646 -47,63.338 LED4H.2
NetP2_1: P2.1 R1.1 | length 4.1
  Top Layer w0.6: R1.1 P2.1
NetP4_1: P4.1 R2.1 | length 4.1
  Top Layer w0.6: P4.1 9.825,-4.975 R2.1
NetP8A_1: P8A.1 U1.23 | length 74.7
  Top Layer w0.3: U1.23 6.69,29.45 7.29,30.05 v1(7.29,43.967)
  Bottom Layer w0.6: v1@7.27,44 46,44 47.661,45.661 P8A.1@47.661,62.396
NetP8A_2: P8A.2 Q1A.3 | length 5.9
  Top Layer w1: Q1A.3 v1(50.201,57.556)
  Bottom Layer w1: v1@50.137,57.556 P8A.2
NetP8B_1: P8B.1 U1.24 | length 60.9
  Top Layer w0.3: U1.24 6.483,29.95 6.69,30.157 6.69,42.585 v1(5.308,43.967)
  Bottom Layer w0.6: v1@5.27,44.038 5.27,45.135 5.796,45.661 30.661,45.661 32.661,47.661 P8B.1@32.661,62.396
NetP8B_2: P8B.2 Q1B.3 | length 5.9
  Top Layer w1: Q1B.3 v1(35.201,57.556)
  Bottom Layer w1: v1@35.137,57.556 P8B.2
NetP8C_1: P8C.1 U1.25 | length 43.3
  Top Layer w0.3: U1.25 3.198,43.889 v1(3.277,43.967)
  Bottom Layer w0.6: v1@3.27,44 3.27,45.27 3.635,45.635 5,47 15.684,47 17.661,48.977 P8C.1@17.661,62.369
NetP8C_2: P8C.2 Q1C.3 | length 5.9
  Top Layer w1: Q1C.3 v1(20.201,57.556)
  Bottom Layer w1: v1@20.137,57.556 P8C.2
NetP8D_1: P8D.1 U1.26 | length 32.1
  Top Layer w0.3: v1(1.27,43.967) 2.698,42.539 U1.26
  Bottom Layer w0.6: v1@1.27,44 1.27,45.135 2.704,46.569 P8D.1
NetP8D_2: P8D.2 Q1D.3 | length 5.9
  Top Layer w1: Q1D.3 v1(5.308,57.556)
  Bottom Layer w1: v1@5.244,57.556 P8D.2
NetP8E_1: P8E.1 U1.27 | length 40.6
  Top Layer w0.3: v1(-0.686,43.967) 2.198,41.083 U1.27
  Bottom Layer w0.6: P8E.1 -11.79,62.186 -11.79,49.436 -10.418,48.064 -3.794,48.064 -0.73,45 v1@-0.73,44
NetP8E_2: P8E.2 Q1E.3 | length 5.9
  Top Layer w1: Q1E.3 v1(-9.25,57.556)
  Bottom Layer w1: v1@-9.314,57.556 P8E.2
NetP8F_1: P8F.1 U1.28 | length 53.8
  Top Layer w0.3: v1(-2.692,43.967) 1.698,39.577 U1.28
  Bottom Layer w0.6: P8F.1@-25.736,62.369 -25.736,48.736 -24,47 -4.595,47 -2.73,45.135 v1@-2.73,44
NetP8F_2: P8F.2 Q1F.3 | length 5.9
  Top Layer w1: Q1F.3 v1(-23.196,57.556)
  Bottom Layer w1: v1@-23.26,57.556 P8F.2
NetP8G_1: P8G.1 U1.31 | length 67.6
  Top Layer w0.3: v1(-4.75,43.967) 0.198,39.019 U1.31
  Bottom Layer w0.6: P8G.1@-40.29,62.369 -40.29,46.83 -39.121,45.661 -5.391,45.661 -4.73,45 v1@-4.73,44
NetP8G_2: P8G.2 Q1G.3 | length 5.9
  Top Layer w1: Q1G.3 v1(-37.75,57.556)
  Bottom Layer w1: v1@-37.814,57.556 P8G.2
NetP8H_1: P8H.1 U1.32 | length 81.5
  Top Layer w0.3: v1(-6.756,43.967) -0.302,37.513 U1.32
  Bottom Layer w0.6: P8H.1 -55.54,45.54 -54,44 v1@-6.73,44
NetP8H_2: P8H.2 Q1H.3 | length 5.9
  Top Layer w1: Q1H.3 v1(-52.936,57.556)
  Bottom Layer w1: v1@-53,57.556 P8H.2
RESET: C4.2 P7.3 R10.1 SW2.2 U1.8 | length 136
  Top Layer w0.3: U1.8 1.198,21.822 1.698,21.322 5.032,21.322 7.66,23.95 41.744,23.95 48.611,17.083 48.611,-9.26 49.251,-9.9 63.9,-9.9 64.313,-10.313 64.313,-10.713 64.3,-10.725 64.3,-11.595 64.313,-11.607 64.313,-12.197 P7.3
  Top Layer w0.6: R10.1 C4.2 65.494,11.365 SW2.2
  Bottom Layer w0.3: P7.3 64.08,-12.43 66.73,-12.43 68,-11.16 68,8.859 SW2.2
pads on no net: P7.2 P7.4 SW1.4 SW2.4 U1.1 U1.2 U1.3 U1.9 U1.10 U1.11 U1.12 U1.17 U1.18 U1.19 U1.20 U1.44 U1.45 U1.46 U1.47 U1.48 U3.5
copper on no net:
  other v2: -65,-27.545 64.897,-27.545 -65,62.455 64.897,62.455
  other v3: -13.88,-27.32 14.57,-27.32

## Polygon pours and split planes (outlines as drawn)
GND on Bottom Layer "BottomLayer-GND" (solid, pour order 2): -70,-32.545 -69.977,-32.522 -69.977,67.455 -70,67.455 70,67.455 70,-32.545
GND on Top Layer "TopLayer-GND" (solid, pour order 0): -70,-32.545 -69.977,-32.522 -69.977,67.455 -70,67.455 70,67.455 70,-32.545

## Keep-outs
Keep-Out Layer:
  the board outline again, w0.025

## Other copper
Top Layer:
  text "BOULA LUBOŠ" at 41,-21.536 h3.54
  text "Výhybky Vlaky / 2/02/2020" at 41,-30.395 h2.54
Bottom Layer:
  text "BOULA LUBOŠ" at 60,-22.053 h3.54
  text "Vlaky Výhybky / 2/02/2020" at 60,-29 h2.54

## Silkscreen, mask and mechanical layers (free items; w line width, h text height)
Top Overlay:
  text "S5" at -1.981,66.954 h1.52 r180
  text "S4" at 12.497,66.954 h1.52 r180
  text "S7" at -30.505,66.878 h1.52 r180
  text "S6" at -16.129,66.878 h1.52 r180
  text "S2" at 42.443,66.878 h1.52 r180
  text "S8" at -45.72,66.777 h1.52 r180
  text "S1" at 56.871,66.777 h1.52 r180
  text "S3" at 27.483,66.7 h1.52 r180
  text "RESET" at 62.03,17.805 h1.52
  text "CAN" at -12.014,3.632 h1.52
  text "DCC" at 7.976,3.505 h1.52
  text "MODE" at 62.03,3.327 h1.52
  text "BOULA LUBOŠ" at 41.072,-21.514 h3.54
  text "POWER" at 30.988,-32.055 h1.52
